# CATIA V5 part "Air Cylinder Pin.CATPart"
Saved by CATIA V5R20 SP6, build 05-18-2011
Part number: Air Cylinder Pin
Bounding box of the stored display mesh (mm): x 0 to 300, y -8.25 to 8.25, z 162.75 to 179.25
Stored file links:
  E:\#00 CATIA V5 Movie\#03 CATIA V5 Data\#07 KIN\Balance Unit (1)\Air Cylinder Pin.CATPart
  E:\#00 CATIA V5 Movie\#03 CATIA V5 Data\#07 KIN\Balance Unit (1)\AIR CYLINDER-P02.CATPart
  D:\#20 Kinematics\Balance Jig Unit\Balance Unit Assembly.CATProduct
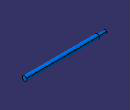
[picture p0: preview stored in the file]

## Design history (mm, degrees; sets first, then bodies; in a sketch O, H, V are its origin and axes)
Set1
  DatumCurve1
  Plane1: type Offset, RefPlane xy-plane, Offset 171
Body1 (main body)
  Body2
    Sketch1 on Plane1, origin (0, 0, 171), H (1, 0, 0), V (0, 1, 0)
      axis line L1 (0, 0) -> (300, 0)
      point P2 (0, 5.323)
      line L2 (0, 5.323) -> (30, 5.323)
      line L3 (30, 5.323) -> (30, 8.25)
      line L4 (30, 8.25) -> (300, 8.25)
      line L5 (300, 8.25) -> (300, 0)
      line L6 (0, 5.323) -> (0, 0)
      distance L1 L4 = 8.25
      distance L1 L2 = 5.323
      distance V L3 = 30
      distance V L5 = 300
      horizontal: L1 H, L2 H, L4 H
      coincidence: P2 V
      vertical: L3 V, L5 V, L6 V
    Shaft1: profile Sketch1, axis Sketch1.L1, angle 360
  Assemble1: tool Body2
